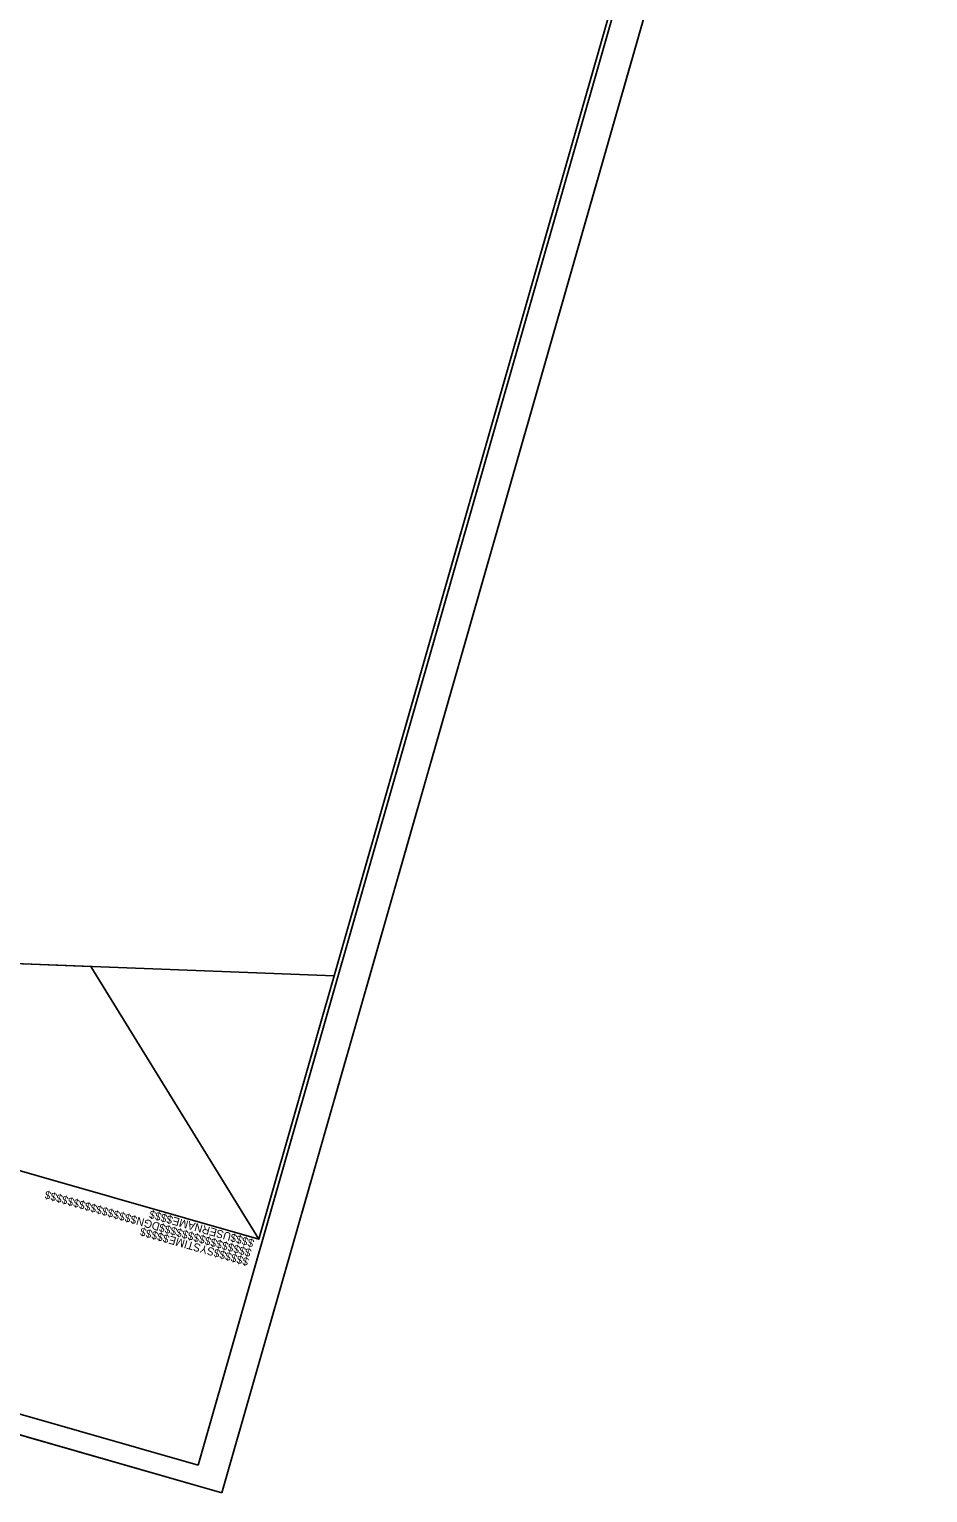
# Model space of a CAD drawing. Extents: x 2096976 to 2098492, y 681809 to 689636.
# Drawn here: x 2097902 to 2098492, y 687716 to 688676 of the extents above; entities that cross this region are included whole.
import ezdxf

# ---------------------------------------------------------------- set-up
doc = ezdxf.new("R2010")
doc.units = 0
for name, color, linetype in [('Matchline Text', 7, 'Continuous'), ('Scratch_Level_6', 7, 'Continuous'), ('Sheet Block Title CELL', 7, 'Continuous'), ('Sheet Data Field CELL', 7, 'Continuous'), ('Sheet Plan And Profile CELL', 7, 'Continuous'), ('Sheet Plot Border Inside CELL', 7, 'Continuous'), ('Sheet Sticker Exception Certification CELL', 7, 'Continuous')]:
    doc.layers.add(name, color=color, linetype=linetype)

msp = doc.modelspace()

# ---------------------------------------------------------------- linework, layer by layer
at = {"layer": 'Matchline Text'}
msp.add_line((2097592.68, 688074.63), (2097942.42, 688061.22), dxfattribs=at)
at = {"layer": 'Scratch_Level_6'}
msp.add_line((2097942.42, 688061.22), (2098052.61, 687882.22), dxfattribs=at)
at = {"layer": 'Sheet Block Title CELL'}
msp.add_lwpolyline([(2098028.44, 687715.97), (2098491.74, 689334.46), (2097439.02, 689635.81), (2096975.72, 688017.32)], close=True, dxfattribs=at)
at = {"layer": 'Sheet Data Field CELL'}
msp.add_lwpolyline([(2098012.79, 687733.97), (2098471.26, 689335.63), (2097457.01, 689625.98), (2096998.53, 688024.31)], close=True, dxfattribs=at)
at = {"layer": 'Sheet Plan And Profile CELL'}
for p, q in [((2098028.44, 687715.97), (2098491.74, 689334.46)), ((2096975.72, 688017.32), (2098028.44, 687715.97))]:
    msp.add_line(p, q, dxfattribs=at)
at = {"layer": 'Sheet Plot Border Inside CELL'}
for points in [[(2098102.1, 688055.1), (2097347.73, 688084.03), (2097043.16, 688171.19), (2097346.07, 689229.4), (2097355.46, 689262.19), (2097400.9, 689420.95), (2097628.1, 689355.93), (2097683.15, 689548.26), (2098465.42, 689324.31)], [(2098102.1, 688055.1), (2097347.73, 688084.03), (2097043.16, 688171.19), (2097345.95, 689228.93), (2097355.46, 689262.19), (2097400.91, 689420.95), (2097628.1, 689355.93), (2097683.15, 689548.26), (2098465.42, 689324.31)]]:
    msp.add_lwpolyline(points, close=True, dxfattribs=at)
at = {"layer": 'Sheet Sticker Exception Certification CELL'}
msp.add_line((2098052.61, 687882.22), (2098052.61, 687882.22), dxfattribs=at)
for points in [[(2097455.97, 689613.3), (2097043.16, 688171.19), (2098052.61, 687882.22), (2098465.42, 689324.31)], [(2098052.61, 687882.22), (2097043.17, 688171.15), (2097400.9, 689420.95), (2097545.17, 689379.67), (2097600.23, 689571.98), (2098465.42, 689324.31)]]:
    msp.add_lwpolyline(points, close=True, dxfattribs=at)

# ---------------------------------------------------------------- texts
for s, p in [('$$$$$$$$$$$$$$$$DGN$$$$$$$$$$$$$$$$', (2098048.24, 687875.53)), ('$$$$USERNAME$$$$', (2098050.03, 687881.83)), ('$$$$$$SYSTIME$$$$$', (2098046.59, 687869.68))]:
    msp.add_text(s, height=5.25, rotation=164.02589, dxfattribs=at).set_placement(p)

doc.saveas('drawing.dxf')
